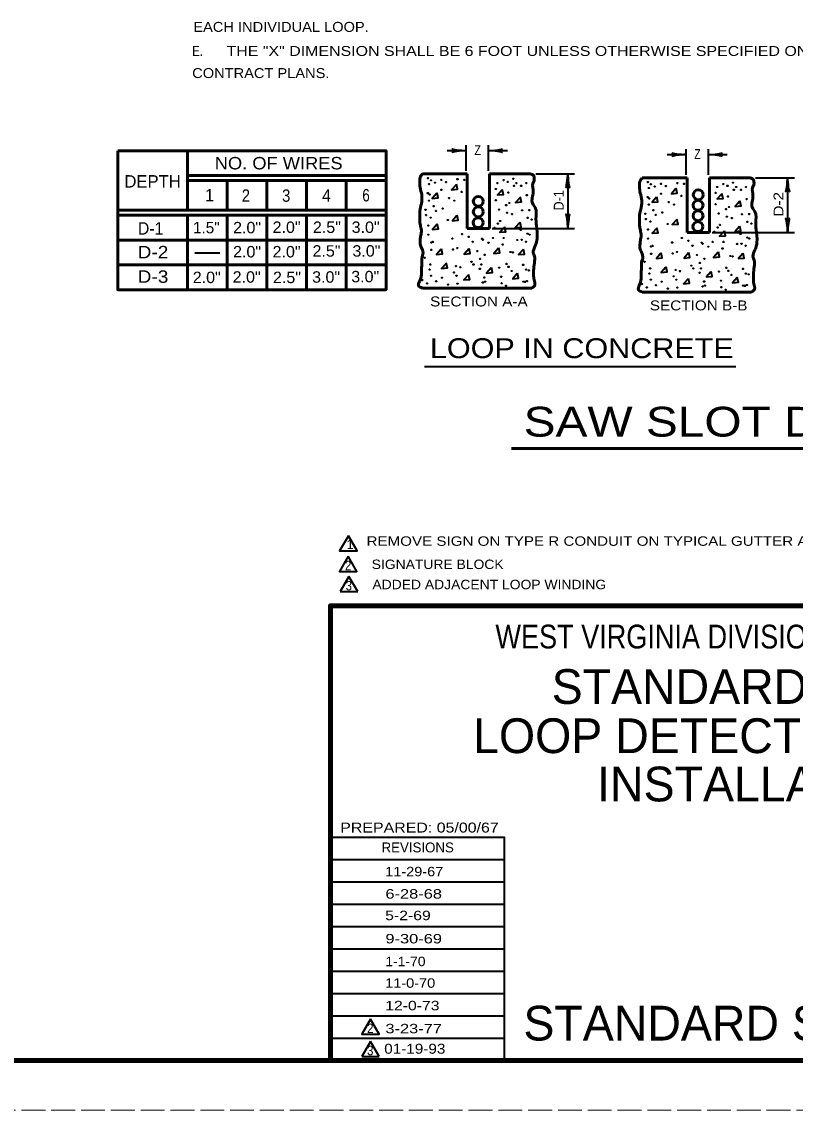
# Model space of a CAD drawing. Extents: x -58 to 622, y -372 to 68.
# Drawn here: x 376.8 to 532.5, y -372 to -152.9 of the extents above; entities that cross this region are included whole.
import ezdxf
from ezdxf.enums import TextEntityAlignment as Align

# ---------------------------------------------------------------- set-up
doc = ezdxf.new("R2010")
doc.units = 0
doc.header["$LTSCALE"] = 0.8
doc.linetypes.add('LONG_DASHED', pattern=[7.5, 6, -1.5])
doc.layers.add('1', color=7, linetype='Continuous', lineweight=35)
doc.layers.add('61', color=7, linetype='Continuous', lineweight=35)

msp = doc.modelspace()

# ---------------------------------------------------------------- linework, layer by layer
at = {"layer": '1', "lineweight": 53}
for p, q in [((410.1558, -178.8394), (410.1558, -190.7343)), ((418.1558, -178.8394), (418.1558, -178.8787)), ((426.1558, -178.8394), (426.1558, -178.8787)), ((434.1558, -178.8394), (434.1558, -178.8787)), ((442.1558, -178.8394), (442.1558, -178.9583)), ((450.1558, -183.8394), (410.1597, -183.8394)), ((457.5023, -183.4934), (466.5023, -183.4934)), ((466.5023, -183.4934), (466.5023, -194.4934)), ((471.0023, -183.4934), (479.0023, -183.4934)), ((471.0023, -183.4934), (471.0023, -194.4934)), ((450.1558, -184.8394), (410.1597, -184.8394)), ((418.1558, -184.8463), (418.1558, -190.8138)), ((426.1558, -184.9259), (426.1558, -190.7343)), ((434.1558, -184.9259), (434.1558, -190.8138)), ((442.1558, -184.8463), (442.1558, -190.7343)), ((501.7418, -184.2891), (510.7418, -184.2891)), ((510.7418, -184.2891), (510.7418, -195.2891)), ((515.2418, -184.2891), (523.2418, -184.2891)), ((515.2418, -184.2891), (515.2418, -195.2891)), ((450.1558, -190.8394), (396.1558, -190.8394)), ((450.1558, -191.8394), (396.1558, -191.8394)), ((410.1558, -191.9278), (410.1558, -206.8394)), ((418.1558, -191.8483), (418.1558, -206.8394)), ((426.1558, -191.9278), (426.1558, -206.8394)), ((434.1558, -191.8483), (434.1558, -206.8394)), ((442.1558, -191.8483), (442.1558, -206.8394)), ((466.5023, -194.4934), (471.0023, -194.4934)), ((450.1558, -196.8394), (396.1558, -196.8394)), ((510.7418, -195.2891), (515.2418, -195.2891)), ((450.1558, -201.8394), (396.1558, -201.8394)), ((457.5023, -206.4934), (479.5023, -206.4934)), ((501.7418, -207.2891), (523.7418, -207.2891)), ((475.4047, -238.811), (566.749, -238.811))]:
    msp.add_line(p, q, dxfattribs=at)
at = {"layer": '1'}
for p, q in [((462.4751, -178.8182), (466.2951, -178.8182)), ((466.3032, -182.8762), (466.3032, -177.7043)), ((470.7501, -178.8182), (474.5701, -178.8182)), ((470.8032, -182.8762), (470.8032, -177.7043)), ((506.7147, -179.6138), (510.5347, -179.6138)), ((510.5427, -183.6718), (510.5427, -178.4999)), ((514.9897, -179.6138), (518.8097, -179.6138)), ((515.0427, -183.6718), (515.0427, -178.4999)), ((480.2982, -183.5127), (488.1103, -183.5127)), ((486.7431, -183.4331), (486.7431, -194.4942)), ((524.5377, -184.3083), (532.3499, -184.3083)), ((530.9827, -184.2287), (530.9827, -195.2898)), ((471.5457, -194.493), (488.1103, -194.493)), ((515.7853, -195.2887), (532.3499, -195.2887)), ((411.6715, -199.4072), (416.6715, -199.4072)), ((442.6945, -264.5677), (440.9445, -267.5988)), ((444.4445, -267.5988), (442.6945, -264.5677)), ((440.9445, -267.5988), (444.4445, -267.5988)), ((473.9702, -321.6067), (438.9903, -321.6067)), ((473.9702, -326.1067), (438.9903, -326.1067)), ((473.9702, -330.6067), (438.9903, -330.6067)), ((473.9702, -335.1267), (438.9903, -335.1267)), ((473.9702, -339.6067), (438.9903, -339.6067)), ((473.9702, -344.0867), (438.9903, -344.0867)), ((473.9702, -348.5867), (438.9903, -348.5867)), ((473.9702, -353.0867), (438.9903, -353.0867)), ((473.9702, -357.6067), (438.9903, -357.6067)), ((446.9969, -358.1807), (445.2469, -361.2118)), ((448.7469, -361.2118), (446.9969, -358.1807)), ((445.2469, -361.2118), (448.7469, -361.2118))]:
    msp.add_line(p, q, dxfattribs=at)
at = {"layer": '1', "lineweight": 40}
msp.add_line((457.8999, -222.2609), (520.5994, -222.2609), dxfattribs=at)
at = {"layer": '1', "lineweight": 53}
msp.add_lwpolyline([(396.1558, -178.8394), (450.1558, -178.8394), (450.1558, -206.8394), (396.1558, -206.8394)], close=True, dxfattribs=at)
at = {"layer": '1'}
for points in [[(464.2712, -185.679), (463.3498, -186.7155), (464.5398, -186.6003), (464.3095, -185.6022)], [(460.3724, -187.3897), (459.4511, -188.4262), (460.6411, -188.3111), (460.4108, -187.313)], [(473.501, -186.7134), (472.5797, -187.7499), (473.7697, -187.6347), (473.5393, -186.6367)], [(477.1213, -188.2252), (476.2, -189.2617), (477.39, -189.1465), (477.1597, -188.1484)], [(504.612, -188.1854), (503.6907, -189.2219), (504.8807, -189.1068), (504.6503, -188.1087)], [(508.5107, -186.4747), (507.5894, -187.5112), (508.7794, -187.396), (508.5491, -186.3979)], [(517.7406, -187.5091), (516.8193, -188.5456), (518.0092, -188.4304), (517.7789, -187.4323)], [(521.3609, -189.0208), (520.4396, -190.0573), (521.6296, -189.9422), (521.3992, -188.9441)], [(464.4303, -191.8852), (463.509, -192.9218), (464.699, -192.8066), (464.4687, -191.8085)], [(508.6699, -192.6809), (507.7486, -193.7174), (508.9386, -193.6022), (508.7082, -192.6042)], [(460.4122, -193.6358), (459.4908, -194.6722), (460.6808, -194.5571), (460.4505, -193.559)], [(473.9784, -194.2325), (473.0571, -195.269), (474.2471, -195.1538), (474.0168, -194.1557)], [(477.0816, -193.2777), (476.1602, -194.3142), (477.3502, -194.1991), (477.1199, -193.201)], [(504.6517, -194.4314), (503.7304, -195.4679), (504.9204, -195.3527), (504.6901, -194.3547)], [(518.218, -195.0282), (517.2967, -196.0647), (518.4867, -195.9495), (518.2563, -194.9514)], [(521.3212, -194.0734), (520.3998, -195.1099), (521.5898, -194.9947), (521.3595, -193.9967)], [(461.2476, -198.6883), (460.3262, -199.7248), (461.5162, -199.6097), (461.2859, -198.6116)], [(466.8173, -198.6087), (465.896, -199.6453), (467.086, -199.5301), (466.8557, -198.532)], [(472.7849, -198.4894), (471.8636, -199.5259), (473.0536, -199.4108), (472.8232, -198.4127)], [(477.7578, -198.7281), (476.8365, -199.7646), (478.0265, -199.6494), (477.7962, -198.6513)], [(505.4872, -199.484), (504.5658, -200.5205), (505.7558, -200.4053), (505.5255, -199.4073)], [(511.0569, -199.4044), (510.1356, -200.4409), (511.3256, -200.3257), (511.0952, -199.3277)], [(517.0245, -199.2851), (516.1032, -200.3216), (517.2932, -200.2064), (517.0628, -199.2083)], [(521.9974, -199.5238), (521.0761, -200.5602), (522.2661, -200.4451), (522.0358, -199.447)], [(462.2423, -201.5129), (461.3209, -202.5494), (462.5109, -202.4342), (462.2806, -201.4362)], [(466.7378, -203.8204), (465.8164, -204.8569), (467.0064, -204.7417), (466.7761, -203.7437)], [(471.3129, -202.428), (470.3916, -203.4645), (471.5816, -203.3493), (471.3512, -202.3512)], [(476.5643, -203.5817), (475.643, -204.6182), (476.833, -204.503), (476.6027, -203.5049)], [(506.4818, -202.3086), (505.5605, -203.3451), (506.7505, -203.2299), (506.5202, -202.2318)], [(515.5525, -203.2237), (514.6312, -204.2602), (515.8212, -204.145), (515.5908, -203.1469)], [(510.9773, -204.6161), (510.056, -205.6526), (511.246, -205.5374), (511.0157, -204.5393)], [(520.8039, -204.3773), (519.8826, -205.4138), (521.0726, -205.2987), (520.8423, -204.3006)], [(473.9702, -362.0867), (473.9702, -317.1267), (438.9903, -317.1267)]]:
    msp.add_lwpolyline(points, dxfattribs=at)
for points in [[(442.5614, -256.398), (440.8114, -259.4291), (444.3114, -259.4291)], [(442.5493, -260.5015), (440.7993, -263.5326), (444.2993, -263.5326)], [(446.9969, -353.7044), (445.2469, -356.7355), (448.7469, -356.7355)]]:
    msp.add_lwpolyline(points, close=True, dxfattribs=at)
at = {"layer": '1', "lineweight": 158}
msp.add_lwpolyline([(438.9702, -362.0467), (438.9702, -270.4667), (610.6302, -270.4667)], dxfattribs=at)
at = {"layer": '1'}
for centre in [(458.6103, -184.3565), (458.8092, -185.55), (459.207, -184.7941), (460.0027, -185.2715), (461.2757, -184.7146), (462.2305, -185.1522), (464.538, -184.5554), (465.8907, -184.7146), (472.5743, -185.3511), (473.8076, -184.7543), (474.6431, -185.1124), (475.757, -184.4758), (475.9162, -185.9081), (476.3936, -185.3511), (477.3483, -185.9081), (478.3827, -185.3511), (502.8498, -185.1522), (503.0487, -186.3457), (503.4466, -185.5897), (504.2422, -186.0672), (505.5153, -185.5102), (506.4701, -185.9478), (508.7776, -185.3511), (510.1302, -185.5102), (516.8139, -186.1467), (518.0472, -185.55), (518.8827, -185.9081), (519.9966, -185.2715), (520.6332, -186.1467), (522.6223, -186.1467), (458.5704, -187.3801), (458.9285, -187.6586), (461.2757, -186.7037), (462.8273, -188.3747), (465.3734, -187.1413), (472.256, -186.5446), (474.7624, -187.2607), (478.5021, -187.7779), (502.81, -188.1757), (503.1681, -188.4543), (505.5153, -187.4994), (509.613, -187.937), (516.4956, -187.3402), (519.002, -188.0563), (520.1558, -186.7037), (521.5879, -186.7037), (458.093, -190.7219), (458.8092, -188.8918), (459.7242, -190.0058), (461.5542, -190.4832), (463.9014, -188.8918), (472.256, -188.8123), (472.8926, -190.6821), (474.3247, -189.8068), (474.9613, -189.3692), (503.0487, -189.6875), (507.0669, -189.1703), (508.141, -189.6875), (516.4956, -189.6079), (518.5643, -190.6025), (519.2009, -190.1649), (522.7417, -188.5736), (458.2124, -191.7961), (459.1274, -192.3132), (460.2016, -190.9606), (462.5886, -192.7907), (474.5238, -191.3187), (475.5183, -191.5972), (477.5472, -190.8413), (478.6612, -192.353), (479.0192, -190.8015), (479.4569, -192.7111), (502.3326, -191.5176), (502.452, -192.5917), (503.9638, -190.8014), (504.4412, -191.7562), (505.7938, -191.2788), (517.1322, -191.4777), (518.7633, -192.1143), (519.7579, -192.3928), (521.7868, -191.6369), (523.2588, -191.5972), (458.65, -193.9046), (472.0173, -194.382), (472.6538, -193.5067), (473.1312, -192.9896), (477.2688, -194.7798), (502.8896, -194.7002), (503.367, -193.1089), (506.8282, -193.5863), (516.8934, -194.3024), (517.3708, -193.7852), (522.9008, -193.1487), (523.6965, -193.5067), (458.65, -195.7347), (459.565, -197.2067), (463.5036, -196.5303), (465.453, -195.6153), (466.7659, -196.1722), (467.6013, -197.1668), (469.4712, -196.5701), (469.6303, -196.769), (471.6592, -196.411), (473.8474, -196.411), (476.5925, -196.8088), (477.4677, -196.769), (478.3032, -197.1668), (478.6214, -195.5358), (479.0591, -195.7347), (502.8896, -196.5303), (509.6926, -196.4109), (511.0055, -196.9679), (515.8988, -197.2067), (516.2569, -195.1777), (518.087, -197.2067), (521.5083, -195.5755), (522.861, -196.3314), (523.2987, -196.5303), (459.2467, -197.326), (459.2865, -198.798), (463.623, -198.7184), (464.4982, -198.4399), (468.5163, -199.0367), (470.784, -197.3657), (473.6485, -197.7238), (475.2, -199.2356), (475.6774, -199.3152), (503.4863, -198.1217), (503.8046, -198.0023), (507.7432, -197.326), (508.7378, -199.2356), (511.8409, -197.9625), (513.7107, -197.3657), (513.8699, -197.5647), (515.0236, -198.1614), (517.8881, -198.5195), (520.8321, -197.6045), (521.7072, -197.5647), (522.5427, -197.9625), (457.9339, -200.3893), (467.3627, -201.185), (469.0733, -200.628), (469.9883, -199.7926), (474.4043, -201.6227), (502.1735, -201.185), (503.5261, -199.5937), (507.8626, -199.5141), (512.7559, -199.8323), (513.3129, -201.4237), (514.2279, -200.5882), (519.4396, -200.0312), (519.917, -200.1108), (458.9285, -202.7763), (459.0876, -201.742), (463.8219, -203.3333), (464.2197, -202.0602), (465.095, -202.2989), (467.7605, -201.742), (469.0336, -202.6172), (469.312, -201.742), (472.9323, -202.3785), (474.8022, -202.2194), (475.4387, -203.0548), (477.7462, -201.8216), (478.3429, -202.7763), (478.8999, -202.9355), (503.1681, -203.572), (503.3272, -202.5377), (508.4593, -202.8559), (509.3346, -203.0946), (511.6022, -201.9807), (512.0001, -202.5377), (513.2732, -203.4129), (513.5516, -202.5377), (517.1719, -203.1742), (518.6439, -202.4183), (519.0417, -203.0151), (519.6783, -203.8505), (521.9857, -202.6172), (522.5825, -203.572), (523.1395, -203.7312), (457.4167, -204.8849), (458.4113, -205.5613), (459.207, -204.0097), (460.2413, -205.1236), (461.3951, -204.4075), (462.6283, -205.7999), (464.3391, -204.0097), (464.538, -205.601), (469.6303, -205.3623), (469.9486, -204.3678), (470.1078, -205.2032), (473.3302, -204.2086), (473.4097, -205.5214), (474.285, -206.0387), (477.786, -205.2032), (478.144, -205.2429), (478.5418, -205.0838), (501.6562, -205.6806), (503.4466, -204.8053), (504.4809, -205.9193), (505.6347, -205.2032), (508.0615, -204.129), (508.5787, -204.8053), (514.1882, -205.1634), (514.3473, -205.9988), (517.5697, -205.0042), (522.0256, -205.9988), (522.3836, -206.0386), (522.7814, -205.8795), (502.6509, -206.3569), (506.8679, -206.5956), (508.7776, -206.3967), (513.8699, -206.158), (517.6493, -206.3171), (518.5246, -206.8343)]:
    msp.add_circle(centre, 0.0607, dxfattribs=at)
at = {"layer": '1', "lineweight": 53}
for centre in [(468.7212, -189.0232), (513.0005, -187.7103), (468.7212, -191.1317), (512.9607, -189.8189), (468.6814, -193.3198), (512.9607, -191.9274), (512.921, -194.1155)]:
    msp.add_circle(centre, 1, dxfattribs=at)
at = {"layer": '1', "lineweight": 40}
for centre, major_axis, ratio, start_param, end_param in [((465.2039, -179.0945), (1.7857, 0.1562), 0.122415, 0.89635335, 3.14159265), ((465.1746, -178.6066), (1.7565, -0.1757), 0.07063, 3.14071475, 5.41810995), ((471.8706, -179.0298), (1.7565, -0.1757), 0.07063, 6.28230741, 8.55970261), ((471.8413, -178.5419), (-1.7857, -0.1562), 0.122415, 0.89635335, 3.14159265), ((509.4435, -179.8901), (1.7857, 0.1562), 0.122415, 0.89635335, 3.14159265), ((509.4142, -179.4022), (1.7565, -0.1757), 0.07063, 3.14071475, 5.41810995), ((516.1102, -179.8254), (1.7565, -0.1757), 0.07063, 6.28230741, 8.55970261), ((516.0809, -179.3375), (-1.7857, -0.1562), 0.122415, 0.89635335, 3.14159265), ((486.5315, -184.5536), (-0.1757, -1.7565), 0.07063, 6.28230741, 8.55970261), ((487.0194, -184.5243), (-0.1562, 1.7857), 0.122415, 0.89635335, 3.14159265), ((530.7711, -185.3493), (-0.1757, -1.7565), 0.07063, 6.28230741, 8.55970261), ((531.259, -185.3199), (-0.1562, 1.7857), 0.122415, 0.89635335, 3.14159265), ((486.4668, -193.403), (0.1562, -1.7857), 0.122415, 0.89635335, 3.14159265), ((486.9547, -193.3737), (0.1757, 1.7565), 0.07063, 6.28230741, 8.55970261), ((530.7064, -194.1986), (0.1562, -1.7857), 0.122415, 0.89635335, 3.14159265), ((531.1943, -194.1693), (0.1757, 1.7565), 0.07063, 6.28230741, 8.55970261)]:
    msp.add_ellipse(centre, major_axis=major_axis, ratio=ratio, start_param=start_param, end_param=end_param, dxfattribs=at)
at = {"layer": '1', "lineweight": 53}
for points in [[(457.5023, -183.4934), (457.1043, -184.0104), (456.9452, -185.0447), (457.0247, -186.2382), (457.343, -187.6705), (457.2635, -189.5006), (456.9452, -191.0123), (456.9452, -191.5693), (456.9452, -193.1607), (457.1043, -194.0359), (457.2635, -195.1498), (457.1043, -196.1047), (457.0247, -196.9799), (457.0247, -197.6164), (457.343, -198.4917), (457.5817, -199.6852), (457.4226, -200.2422), (457.343, -200.8787), (457.343, -201.8335), (457.2635, -202.7087), (457.2635, -203.8227), (456.8656, -205.1753), (456.7065, -206.0506), (457.5023, -206.4934)], [(479.0023, -183.4934), (479.7015, -183.6922), (479.9402, -184.8857), (479.7015, -185.4426), (479.781, -187.1135), (479.6219, -189.421), (480.1788, -190.2962), (480.338, -192.6037), (480.4176, -193.8767), (480.5767, -196.5025), (480.1788, -198.0143), (479.781, -199.3669), (480.0197, -200.083), (480.0197, -201.4357), (479.8606, -202.9474), (479.8606, -203.8227), (479.9402, -204.8571), (480.0993, -205.8914), (479.5023, -206.4934)], [(501.7418, -184.2891), (501.3439, -184.8061), (501.1848, -185.8404), (501.2643, -187.0339), (501.5826, -188.4662), (501.5031, -190.2962), (501.1848, -191.808), (501.1848, -192.365), (501.1848, -193.9563), (501.3439, -194.8316), (501.5031, -195.9455), (501.3439, -196.9003), (501.2643, -197.7756), (501.2643, -198.4121), (501.5826, -199.2873), (501.8213, -200.4808), (501.6622, -201.0378), (501.5826, -201.6743), (501.5826, -202.6292), (501.5031, -203.5044), (501.5031, -204.6183), (501.1052, -205.971), (500.9461, -206.8462), (501.7418, -207.2891)], [(523.2418, -184.2891), (523.9411, -184.4878), (524.1798, -185.6813), (523.9411, -186.2382), (524.0206, -187.9092), (523.8615, -190.2167), (524.4184, -191.0919), (524.5776, -193.3993), (524.6572, -194.6724), (524.8162, -197.2982), (524.4184, -198.8099), (524.0206, -200.1626), (524.2593, -200.8787), (524.2593, -202.2313), (524.1002, -203.7431), (524.1002, -204.6183), (524.1798, -205.6527), (524.3389, -206.6871), (523.7418, -207.2891)]]:
    msp.add_spline(points, degree=3, dxfattribs=at)
at = {"layer": '61', "lineweight": 158}
msp.add_line((610.6302, -362.0467), (-28.4297, -362.0267), dxfattribs=at)
at = {"layer": '61', "linetype": 'LONG_DASHED', "lineweight": 13}
msp.add_line((621.5702, -372.0267), (-58.4898, -372.0467), dxfattribs=at)

# ---------------------------------------------------------------- texts
at = {"layer": '1'}
for s, height, width, p in [('EACH INDIVIDUAL LOOP.', 2, 1.1, (411.3583, -154.8992)), ('E.', 2, 0.85, (411.1331, -159.7506)), ('THE "X" DIMENSION SHALL BE 6 FOOT UNLESS OTHERWISE SPECIFIED ON THE', 2, 1.2, (418.0359, -159.7507)), ('CONTRACT PLANS.', 2, 1.1, (411.1331, -164.2022)), ('REMOVE SIGN ON TYPE R CONDUIT ON TYPICAL GUTTER AND SIDEWALK PLAN.', 1.9, 1.2, (446.2252, -258.3905)), ('2', 1.9, 0.9, (441.8777, -263.3051)), ('SIGNATURE BLOCK', 1.9, 1.1, (447.2649, -263.0684)), ('3', 1.9, 0.9, (442.0229, -267.3713)), ('ADDED ADJACENT LOOP WINDING', 1.9, 1.1, (447.4101, -267.1347)), ('PREPARED: 05/00/67', 1.998, 1.2, (440.9303, -316.1267)), ('11-29-67', 1.9, 1.15, (449.976, -324.9387)), ('6-28-68', 1.9, 1.3, (450.0232, -329.428)), ('5-2-69', 1.9, 1.25, (449.9759, -333.7755)), ('9-30-69', 1.9, 1.3, (450.0232, -338.4539)), ('1-1-70', 1.9, 1.1, (450.0232, -343.0378)), ('11-0-70', 1.9, 1.15, (449.9759, -347.3852)), ('12-0-73', 1.9, 1.25, (449.9759, -351.9219)), ('2', 1.9, 0.9, (446.3372, -356.5057)), ('3-23-77', 1.9, 1.3, (450.0232, -356.553)), ('3', 1.9, 0.9, (446.3372, -360.9821))]:
    msp.add_text(s, height=height, dxfattribs=dict(at, width=width)).set_placement(p)
for s, height, width, p in [('Z', 2, 0.8, (468.6017, -179.7185)), ('Z', 2, 0.8, (512.8413, -180.5142)), ('NO. OF WIRES', 2.5, 1.1, (428.5398, -182.5953)), ('2', 2.5, 0.9, (421.9357, -189.1198)), ('3', 2.5, 0.9, (430.0516, -189.1198)), ('4', 2.5, 0.95, (438.1674, -189.1198)), ('6', 2.5, 0.8, (446.1242, -189.0403)), ('D-1', 2.5, 0.95, (402.76, -195.724)), ('2.0"', 2.3, 1.05, (422.1744, -195.4648)), ('2.0"', 2.3, 1.05, (430.1312, -195.3852)), ('2.5"', 2.3, 1.05, (438.247, -195.3852)), ('3.0"', 2.3, 1.05, (446.0446, -195.3853)), ('D-2', 2.5, 1.15, (403.2375, -200.498)), ('2.0"', 2.3, 1.05, (422.1743, -200.3184)), ('2.0"', 2.3, 1.05, (430.1311, -200.3185)), ('2.5"', 2.3, 1.05, (438.1675, -200.1593)), ('3.0"', 2.3, 1.05, (446.2037, -200.1593)), ('D-3', 2.5, 1.15, (403.2375, -205.4313)), ('2.0"', 2.3, 1.05, (414.0586, -205.4903)), ('2.0"', 2.3, 1.05, (422.0948, -205.4108)), ('2.5"', 2.3, 1.05, (430.2107, -205.4904)), ('3.0"', 2.3, 1.05, (438.0878, -205.4108)), ('3.0"', 2.3, 1.05, (445.9651, -205.3312)), ('SECTION A-A', 2, 1.15, (468.8405, -210.1928)), ('SECTION B-B', 2, 1.15, (513.0801, -210.9885)), ('LOOP IN CONCRETE', 4, 1.15, (489.5678, -220.6008)), ('SAW SLOT DETAIL', 6, 1.2, (520.9174, -236.4004)), ('WEST VIRGINIA DIVISION OF HIGHWAYS', 4.795, 0.85, (525.6186, -279.0667)), ('01-19-93', 2, 1.15, (455.9396, -360.6667))]:
    msp.add_text(s, height=height, dxfattribs=dict(at, width=width)).set_placement(p, align=Align.CENTER)
for s, height, p in [('DEPTH', 2.5, (403.1577, -186.2554)), ('1', 2.5, (414.6215, -189.0403)), ('1.5"', 2.3, (413.979, -195.4648)), ('STANDARD DETAIL', 6.993, (526.8872, -290.2267)), ('LOOP DETECTOR TYPE III', 7, (526.4484, -300.1333)), ('INSTALLATION', 7, (525.9161, -309.8602))]:
    msp.add_text(s, height=height, dxfattribs=at).set_placement(p, align=Align.CENTER)
for s, width, p in [('D-1', 0.95, (485.9132, -188.8236)), ('D-2', 1.15, (530.1527, -189.6192))]:
    msp.add_text(s, height=2, rotation=90, dxfattribs=dict(at, width=width)).set_placement(p, align=Align.CENTER)
for s, height, p in [('1', 1.9, (442.2085, -259.0521)), ('REVISIONS', 1.998, (449.2502, -320.1267)), ('STANDARD SHEET TES-01', 6.993, (477.8102, -358.0067))]:
    msp.add_text(s, height=height, dxfattribs=at).set_placement(p)

doc.saveas('drawing.dxf')
